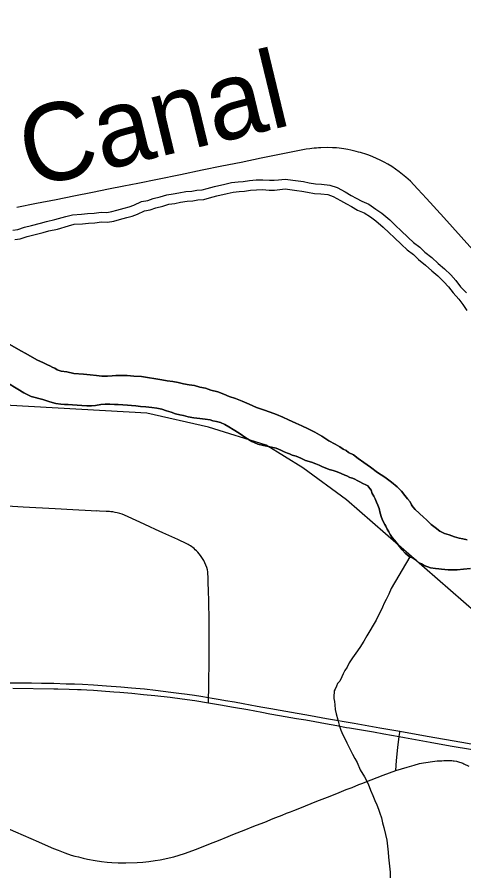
# Model space of a CAD drawing. Extents: x 0 to 34, y -1.2 to 22.
# Drawn here: x 4.736 to 5.172, y 17.227 to 18.067 of the extents above; entities that cross this region are included whole.
import ezdxf

# ---------------------------------------------------------------- set-up
doc = ezdxf.new("R2010")
doc.units = 0
for name, color, linetype in [('GM_X_City_Street', 7, 'Continuous'), ('GM_X_County_Road', 7, 'Continuous'), ('GM_X_Rail_Line', 7, 'Continuous'), ('GM_X_State_Route', 7, 'Continuous'), ('SH_Data', 7, 'Continuous'), ('SH_Text', 7, 'Continuous'), ('UT_X_Telecom', 7, 'Continuous')]:
    doc.layers.add(name, color=color, linetype=linetype)

msp = doc.modelspace()

# ---------------------------------------------------------------- linework, layer by layer
at = {"layer": 'GM_X_City_Street'}
for points in [[(4.70937, 17.59029), (4.74135, 17.58835), (4.7728, 17.58644), (4.79013, 17.5855), (4.80783, 17.58454), (4.8131, 17.58426)], [(4.92269, 17.39645), (4.92269, 17.40167), (4.92294, 17.40926), (4.92301, 17.41883), (4.92325, 17.43444), (4.92346, 17.44977), (4.92334, 17.47715), (4.92321, 17.48481), (4.92314, 17.48809), (4.92299, 17.49699), (4.92289, 17.49976), (4.92274, 17.50258), (4.92262, 17.50636), (4.92248, 17.51386), (4.92238, 17.5163), (4.92229, 17.51879), (4.92216, 17.52365), (4.92207, 17.52375), (4.92199, 17.52452), (4.92159, 17.52659), (4.9209, 17.52905), (4.92012, 17.53108), (4.91914, 17.5334), (4.91804, 17.53563), (4.91744, 17.53673), (4.91623, 17.53875), (4.91563, 17.53966), (4.91499, 17.54054), (4.91365, 17.54226), (4.91219, 17.54388), (4.91101, 17.54509), (4.90978, 17.54627), (4.90853, 17.54742), (4.90733, 17.54845), (4.90627, 17.54917), (4.9051, 17.54994), (4.9039, 17.55068), (4.90269, 17.55139), (4.90152, 17.55205), (4.89251, 17.5563), (4.88972, 17.55746), (4.87785, 17.56289), (4.87078, 17.56614), (4.86532, 17.56869), (4.86041, 17.57086), (4.8554, 17.57326), (4.84065, 17.58001), (4.83823, 17.581), (4.83586, 17.58178), (4.8335, 17.5824), (4.83146, 17.5828), (4.82917, 17.58321), (4.82724, 17.58342), (4.8258, 17.5835), (4.82258, 17.58375), (4.81603, 17.58408), (4.8131, 17.58426)], [(4.8117, 17.24247), (4.81817, 17.24147), (4.8235, 17.24092), (4.82828, 17.24061), (4.83434, 17.24033), (4.84188, 17.24006), (4.85278, 17.24048), (4.85831, 17.24083), (4.86427, 17.24148), (4.87054, 17.24235), (4.87526, 17.24317), (4.88865, 17.24601), (4.89906, 17.24941), (4.91078, 17.25369), (4.92146, 17.25781), (4.92706, 17.26014), (4.93241, 17.26212), (4.942, 17.26602), (4.94654, 17.26779), (4.95065, 17.2694), (4.95487, 17.27112), (4.9593, 17.27285), (4.96536, 17.27524), (4.96951, 17.27697), (4.97405, 17.27873), (4.97932, 17.28067), (4.98418, 17.2827), (4.98849, 17.28446), (4.99459, 17.28678), (4.99889, 17.28859), (5.00273, 17.29005), (5.00621, 17.29144), (5.01193, 17.29372), (5.02308, 17.2981), (5.02867, 17.30032), (5.03391, 17.30234), (5.03888, 17.30432), (5.04479, 17.30673), (5.05027, 17.30898), (5.05731, 17.31172), (5.0631, 17.31396), (5.06964, 17.3167), (5.07364, 17.31817), (5.07763, 17.31969), (5.0816, 17.32125), (5.0933, 17.32592), (5.10595, 17.33053), (5.10657, 17.34028), (5.10774, 17.35282), (5.10917, 17.3637), (5.10964, 17.36757), (5.10979, 17.3688)], [(5.10595, 17.33053), (5.11693, 17.33382), (5.12389, 17.33572), (5.12902, 17.33712), (5.13293, 17.33792), (5.13513, 17.33832), (5.13734, 17.33869), (5.13955, 17.33901), (5.14176, 17.3393), (5.14399, 17.33955), (5.14621, 17.33975), (5.14844, 17.33992), (5.15067, 17.34004), (5.15291, 17.34012), (5.15648, 17.34023), (5.15878, 17.34016), (5.16071, 17.34008), (5.1618, 17.34), (5.16289, 17.33987), (5.16505, 17.33951), (5.16612, 17.33928), (5.16718, 17.339), (5.16823, 17.33869), (5.16927, 17.33834), (5.17029, 17.33795), (5.1713, 17.33752), (5.1723, 17.33707), (5.17716, 17.33453)], [(4.68636, 17.29112), (4.70286, 17.28399), (4.73392, 17.27048), (4.75652, 17.26055), (4.76594, 17.2565), (4.77106, 17.25427), (4.77568, 17.25241), (4.78208, 17.25005), (4.78853, 17.24775), (4.79194, 17.24676), (4.79543, 17.24588), (4.80017, 17.24465), (4.8042, 17.24375), (4.8117, 17.24247)]]:
    msp.add_lwpolyline(points, dxfattribs=at)
at = {"layer": 'GM_X_County_Road'}
msp.add_lwpolyline([(5.18944, 17.83012), (5.16969, 17.85202), (5.15261, 17.87089), (5.13584, 17.88969), (5.12735, 17.89889), (5.12357, 17.90294), (5.12001, 17.90641), (5.11565, 17.91032), (5.11242, 17.91313), (5.10897, 17.91581), (5.10541, 17.91836), (5.10177, 17.92077), (5.09803, 17.92304), (5.09435, 17.92517), (5.09066, 17.92709), (5.08706, 17.92886), (5.08324, 17.93038), (5.07928, 17.93186), (5.07536, 17.93319), (5.07332, 17.93386), (5.07126, 17.93448), (5.06919, 17.93507), (5.0671, 17.93562), (5.06186, 17.93685), (5.0589, 17.93746), (5.05493, 17.93811), (5.05037, 17.93874), (5.04793, 17.939), (5.04402, 17.93927), (5.03948, 17.93936), (5.03253, 17.93923), (5.03031, 17.93911), (5.02813, 17.93895), (5.02595, 17.93875), (5.02378, 17.9385), (5.02162, 17.93821), (5.01831, 17.93779), (5.00853, 17.93597), (4.99683, 17.93366), (4.97404, 17.92889), (4.95474, 17.92497), (4.93556, 17.92108), (4.91653, 17.91722), (4.89522, 17.91289), (4.8727, 17.90833), (4.8535, 17.90444), (4.83981, 17.90165), (4.82487, 17.89872), (4.80913, 17.89552), (4.79109, 17.89184), (4.77378, 17.88832), (4.75456, 17.88457), (4.73523, 17.8808)], dxfattribs=at)
at = {"layer": 'GM_X_Rail_Line'}
msp.add_lwpolyline([(5.36803, 17.32517), (5.35374, 17.3375), (5.21012, 17.46206), (5.05765, 17.59497), (5.01492, 17.62627), (4.97905, 17.6484), (4.92259, 17.66596), (4.8623, 17.6797), (4.56699, 17.69649), (4.4945, 17.70412), (4.44719, 17.71557), (4.40217, 17.73389), (4.35562, 17.75985), (4.31289, 17.79343), (4.27626, 17.83465), (4.23353, 17.89419), (4.02937, 18.17245)], dxfattribs=at)
at = {"layer": 'GM_X_State_Route'}
for points in [[(4.72487, 17.41628), (4.7495, 17.41601), (4.75945, 17.4159), (4.77153, 17.41573)], [(4.77153, 17.41573), (4.78364, 17.41531), (4.79152, 17.41508), (4.79948, 17.41477), (4.81013, 17.41424), (4.8229, 17.41334), (4.83691, 17.41221), (4.84751, 17.41135), (4.85996, 17.41017), (4.87077, 17.40891), (4.8859, 17.40714), (4.89373, 17.40613), (4.90195, 17.40504), (4.90907, 17.40401), (4.91503, 17.403), (4.92269, 17.40167), (4.92609, 17.40109), (4.93419, 17.39984), (4.93921, 17.39891), (4.94798, 17.39743), (4.95663, 17.39579), (4.9702, 17.39342), (4.97584, 17.39244), (4.98368, 17.391), (4.99281, 17.3894), (5.00947, 17.38647), (5.01874, 17.38487), (5.02747, 17.38326), (5.03809, 17.3814), (5.06504, 17.37669), (5.09016, 17.37226), (5.10979, 17.3688), (5.13659, 17.36407), (5.17047, 17.35808), (5.19036, 17.35459)], [(4.73136, 17.4108), (4.77128, 17.41027), (4.77519, 17.41016), (4.78652, 17.40991), (4.7947, 17.4097), (4.79813, 17.40947), (4.80358, 17.40923), (4.81016, 17.40886), (4.81809, 17.40836), (4.83015, 17.40745), (4.83584, 17.40701), (4.84758, 17.40599), (4.85916, 17.40487), (4.87021, 17.4038), (4.88527, 17.40204), (4.897, 17.40046), (4.90923, 17.39872), (4.92269, 17.39645), (4.93444, 17.39455), (4.94707, 17.39238), (4.96101, 17.39), (4.97493, 17.38739), (4.98277, 17.38595), (4.99193, 17.38434), (5.00859, 17.38142), (5.01783, 17.37981), (5.02656, 17.3782), (5.0372, 17.37634), (5.04816, 17.37436), (5.05767, 17.37256), (5.06067, 17.37208), (5.08391, 17.36809), (5.09417, 17.36635), (5.10917, 17.3637), (5.11423, 17.36281), (5.13928, 17.35829), (5.15907, 17.35453), (5.18082, 17.35094)]]:
    msp.add_lwpolyline(points, dxfattribs=at)
at = {"layer": 'SH_Data'}
for points in [[(4.73134, 17.85872), (4.73633, 17.85944), (4.74274, 17.8616), (4.74953, 17.86322), (4.75849, 17.86549), (4.76426, 17.86705), (4.77255, 17.86896), (4.78328, 17.87196), (4.78961, 17.87379), (4.79864, 17.87422), (4.80426, 17.87499), (4.81077, 17.87539), (4.8178, 17.87623), (4.82321, 17.87589), (4.82803, 17.87675), (4.83295, 17.87817), (4.84015, 17.88009), (4.84506, 17.88151), (4.84973, 17.8832), (4.85718, 17.88654), (4.86321, 17.88777), (4.86841, 17.88964), (4.87541, 17.89122), (4.88186, 17.89326), (4.88805, 17.8941), (4.89353, 17.89522), (4.90058, 17.89648), (4.90637, 17.89688), (4.91129, 17.89766), (4.91646, 17.89801), (4.92126, 17.89931), (4.92861, 17.90127), (4.93851, 17.90359), (4.94531, 17.90531), (4.95181, 17.90576), (4.95655, 17.90611), (4.96263, 17.90727), (4.9692, 17.90773), (4.97585, 17.90774), (4.9823, 17.90738), (4.98695, 17.90739), (4.99121, 17.90773), (4.9975, 17.90864), (5.01026, 17.90697), (5.0155, 17.90618), (5.02124, 17.90504), (5.02743, 17.90402), (5.03323, 17.90367), (5.04138, 17.90278), (5.04837, 17.9003), (5.05641, 17.89608), (5.06213, 17.89266), (5.06695, 17.89007), (5.07259, 17.88691), (5.07943, 17.8841), (5.08641, 17.87932), (5.0921, 17.87527), (5.09991, 17.8687), (5.10576, 17.86286), (5.1106, 17.85841), (5.11783, 17.85156), (5.12313, 17.84663), (5.12933, 17.84199), (5.13432, 17.837), (5.14103, 17.8318), (5.14718, 17.82604), (5.15337, 17.82102), (5.15955, 17.81486), (5.16456, 17.80944), (5.1691, 17.8034), (5.17487, 17.79726)], [(4.73325, 17.84942), (4.73855, 17.85019), (4.74536, 17.85249), (4.7518, 17.85402), (4.76089, 17.85632), (4.76656, 17.85786), (4.7749, 17.85978), (4.78588, 17.86284), (4.79118, 17.86438), (4.79951, 17.86478), (4.80519, 17.86555), (4.81163, 17.86595), (4.81807, 17.86672), (4.82375, 17.86636), (4.83019, 17.86751), (4.83549, 17.86905), (4.84268, 17.87096), (4.84798, 17.8725), (4.85328, 17.87441), (4.8601, 17.87746), (4.86578, 17.87862), (4.87108, 17.88053), (4.87789, 17.88207), (4.88395, 17.88398), (4.88963, 17.88476), (4.89531, 17.88591), (4.90175, 17.88706), (4.90743, 17.88746), (4.91235, 17.88823), (4.91803, 17.88863), (4.92371, 17.89016), (4.93091, 17.89208), (4.94075, 17.89438), (4.94681, 17.89591), (4.95249, 17.89631), (4.9578, 17.8967), (4.96385, 17.89786), (4.96954, 17.89825), (4.9756, 17.89827), (4.98204, 17.8979), (4.98734, 17.89792), (4.99227, 17.89831), (4.99757, 17.89908), (5.00894, 17.89759), (5.01387, 17.89684), (5.01955, 17.89571), (5.02637, 17.89459), (5.03243, 17.89423), (5.03925, 17.89348), (5.04456, 17.8916), (5.05177, 17.88782), (5.05746, 17.88441), (5.06239, 17.88177), (5.06846, 17.87836), (5.07491, 17.87572), (5.08098, 17.87155), (5.08629, 17.86777), (5.0935, 17.86171), (5.0992, 17.85602), (5.10413, 17.85148), (5.11135, 17.84466), (5.11704, 17.83935), (5.12311, 17.83481), (5.12805, 17.82988), (5.13488, 17.82458), (5.14095, 17.8189), (5.14703, 17.81397), (5.15272, 17.80829), (5.15728, 17.80336), (5.16184, 17.79729), (5.16754, 17.79123), (5.17134, 17.78592), (5.17514, 17.78023)], [(5.11955, 17.53947), (5.10113, 17.50842), (5.09893, 17.5027), (5.09634, 17.49772), (5.0945, 17.4939), (5.09265, 17.49008), (5.09081, 17.48588), (5.08859, 17.48167), (5.08675, 17.47747), (5.07747, 17.46215), (5.0745, 17.4568), (5.07079, 17.45067), (5.06669, 17.4453), (5.06333, 17.4407), (5.06036, 17.43572), (5.05814, 17.43152), (5.05591, 17.42807), (5.05444, 17.42501), (5.05296, 17.42195), (5.05112, 17.41775), (5.04887, 17.41544), (5.04777, 17.41277), (5.04667, 17.41009), (5.04555, 17.40818), (5.04558, 17.40628), (5.04523, 17.404), (5.04527, 17.40096), (5.0457, 17.39792), (5.04612, 17.39451), (5.04656, 17.38995), (5.04738, 17.38578), (5.04898, 17.3801), (5.05057, 17.3748), (5.05215, 17.36988), (5.05411, 17.36534), (5.05645, 17.36119), (5.05802, 17.35741), (5.05997, 17.35363), (5.06153, 17.35023), (5.06348, 17.34645), (5.06582, 17.3423), (5.06816, 17.33815), (5.07091, 17.33096), (5.07518, 17.32417), (5.07869, 17.31738), (5.08105, 17.31132), (5.0834, 17.30603), (5.08537, 17.30112), (5.08732, 17.29696), (5.0889, 17.2928), (5.09009, 17.28863), (5.09167, 17.28409), (5.09288, 17.27916), (5.09408, 17.27462), (5.0957, 17.2678), (5.09691, 17.26249), (5.09775, 17.25642), (5.09821, 17.25073), (5.09865, 17.24579), (5.10038, 17.23099), (5.10045, 17.22567)]]:
    msp.add_lwpolyline(points, dxfattribs=at)
at = {"layer": 'UT_X_Telecom'}
for points in [[(4.76745, 17.72595), (4.76516, 17.72706), (4.76133, 17.72892), (4.75484, 17.73188), (4.74642, 17.73672), (4.73685, 17.74192), (4.72843, 17.74676)], [(4.72843, 17.74676), (4.73685, 17.74192), (4.74642, 17.73672), (4.75484, 17.73188), (4.76133, 17.72892), (4.76516, 17.72706), (4.76745, 17.72595)], [(5.17566, 17.55606), (5.17147, 17.55677), (5.16766, 17.55749), (5.16309, 17.55895), (5.15813, 17.56079), (5.15355, 17.56226), (5.14897, 17.56448), (5.14436, 17.56785), (5.14052, 17.57084), (5.13822, 17.57309), (5.13591, 17.57535), (5.13283, 17.57797), (5.12476, 17.58547), (5.12244, 17.58811), (5.12128, 17.58999), (5.11972, 17.59301), (5.1174, 17.59602), (5.1147, 17.59941), (5.11122, 17.60355), (5.10699, 17.60768), (5.10161, 17.61217), (5.09509, 17.61704), (5.08781, 17.62189), (5.0809, 17.62713), (5.07439, 17.63161), (5.06902, 17.63534), (5.06441, 17.63909), (5.05945, 17.64131), (5.05714, 17.64318), (5.05446, 17.64467), (5.05102, 17.64691), (5.04642, 17.64951), (5.0403, 17.65286), (5.03341, 17.65734), (5.02652, 17.66105), (5.02002, 17.66439), (5.01391, 17.66736), (5.00818, 17.66995), (5.00092, 17.67329), (4.99519, 17.67588), (4.98908, 17.67846), (4.98297, 17.68067), (4.97648, 17.68287), (4.96962, 17.68545), (4.96236, 17.6884), (4.95549, 17.69136), (4.949, 17.69394), (4.94289, 17.69615), (4.93755, 17.69836), (4.93182, 17.70057), (4.92496, 17.70239), (4.91962, 17.70423), (4.91429, 17.7053), (4.90895, 17.70676), (4.90363, 17.70745), (4.8983, 17.70853), (4.89297, 17.7096), (4.88764, 17.71068), (4.88231, 17.71138), (4.87698, 17.71245), (4.8572, 17.71563), (4.8496, 17.71592), (4.84313, 17.7166), (4.83744, 17.71653), (4.83213, 17.71647), (4.82833, 17.71642), (4.82378, 17.71599), (4.81846, 17.71592), (4.81314, 17.71662), (4.80705, 17.71731), (4.80059, 17.71799), (4.79109, 17.71863), (4.78423, 17.72007), (4.77853, 17.72076), (4.77471, 17.72224), (4.77241, 17.72373), (4.77051, 17.72447), (4.76745, 17.72595)], [(4.76745, 17.72595), (4.77051, 17.72447), (4.77241, 17.72373), (4.77471, 17.72224), (4.77853, 17.72076), (4.78423, 17.72007), (4.79109, 17.71863), (4.80059, 17.71799), (4.80705, 17.71731), (4.81314, 17.71662), (4.81846, 17.71592), (4.82378, 17.71599), (4.82833, 17.71642), (4.83213, 17.71647), (4.83744, 17.71653), (4.84313, 17.7166), (4.8496, 17.71592), (4.8572, 17.71563), (4.87698, 17.71245), (4.88231, 17.71138), (4.88764, 17.71068), (4.89297, 17.7096), (4.8983, 17.70853), (4.90363, 17.70745), (4.90895, 17.70676), (4.91429, 17.7053), (4.91962, 17.70423), (4.92496, 17.70239), (4.93182, 17.70057), (4.93755, 17.69836), (4.94289, 17.69615), (4.949, 17.69394), (4.95549, 17.69136), (4.96236, 17.6884), (4.96962, 17.68545), (4.97648, 17.68287), (4.98297, 17.68067), (4.98908, 17.67846), (4.99519, 17.67588), (5.00092, 17.67329), (5.00818, 17.66995), (5.01391, 17.66736), (5.02002, 17.66439), (5.02652, 17.66105), (5.03341, 17.65734), (5.0403, 17.65286), (5.04642, 17.64951), (5.05102, 17.64691), (5.05446, 17.64467), (5.05714, 17.64318), (5.05945, 17.64131), (5.06441, 17.63909), (5.06902, 17.63534), (5.07439, 17.63161), (5.0809, 17.62713), (5.08781, 17.62189), (5.09509, 17.61704), (5.10161, 17.61217), (5.10699, 17.60768), (5.11122, 17.60355), (5.1147, 17.59941), (5.1174, 17.59602), (5.11972, 17.59301), (5.12128, 17.58999), (5.12244, 17.58811), (5.12476, 17.58547), (5.13283, 17.57797), (5.13591, 17.57535), (5.13822, 17.57309), (5.14052, 17.57084), (5.14436, 17.56785), (5.14897, 17.56448), (5.15355, 17.56226), (5.15813, 17.56079), (5.16309, 17.55895), (5.16766, 17.55749), (5.17147, 17.55677), (5.17566, 17.55606)], [(4.72552, 17.70986), (4.73625, 17.70315), (4.74199, 17.6998), (4.74925, 17.69609), (4.76068, 17.69319), (4.76755, 17.69099), (4.77327, 17.68916), (4.77821, 17.68846), (4.78202, 17.68812), (4.78543, 17.68817), (4.78961, 17.68784), (4.79417, 17.68751), (4.79873, 17.68718), (4.80367, 17.68686), (4.80823, 17.68692), (4.81202, 17.68734), (4.81732, 17.68817), (4.8215, 17.6886), (4.82605, 17.68866), (4.83061, 17.68833), (4.83441, 17.68838), (4.83897, 17.68805), (4.84353, 17.68773), (4.84733, 17.68739), (4.85151, 17.68706), (4.85608, 17.68636), (4.8614, 17.68604), (4.8671, 17.68535), (4.87205, 17.68465), (4.877, 17.68357), (4.88158, 17.6821), (4.88615, 17.68064), (4.89035, 17.67917), (4.89454, 17.67808), (4.89834, 17.67737)], [(4.89834, 17.67737), (4.89454, 17.67808), (4.89035, 17.67917), (4.88615, 17.68064), (4.88158, 17.6821), (4.877, 17.68357), (4.87205, 17.68465), (4.8671, 17.68535), (4.8614, 17.68604), (4.85608, 17.68636), (4.85151, 17.68706), (4.84733, 17.68739), (4.84353, 17.68773), (4.83897, 17.68805), (4.83441, 17.68838), (4.83061, 17.68833), (4.82605, 17.68866), (4.8215, 17.6886), (4.81732, 17.68817), (4.81202, 17.68734), (4.80823, 17.68692), (4.80367, 17.68686), (4.79873, 17.68718), (4.79417, 17.68751), (4.78961, 17.68784), (4.78543, 17.68817), (4.78202, 17.68812), (4.77821, 17.68846), (4.77327, 17.68916), (4.76755, 17.69099), (4.76068, 17.69319), (4.74925, 17.69609), (4.74199, 17.6998), (4.73625, 17.70315), (4.72552, 17.70986)], [(4.89834, 17.67737), (4.90292, 17.67628), (4.90825, 17.67521), (4.91433, 17.67452), (4.91928, 17.67382), (4.92422, 17.67312), (4.92689, 17.67239), (4.93032, 17.67167), (4.93451, 17.67058), (4.93871, 17.66873), (4.94254, 17.6665), (4.94675, 17.66389), (4.9525, 17.66016), (4.95901, 17.65568), (4.96514, 17.65195), (4.97087, 17.64936), (4.97658, 17.64829), (4.98877, 17.6454), (4.99335, 17.64355), (4.99679, 17.64207), (4.99985, 17.64059), (5.00175, 17.63985), (5.00443, 17.63875), (5.00824, 17.63765), (5.01282, 17.63581), (5.01741, 17.63358), (5.02351, 17.63175), (5.0277, 17.63029), (5.03076, 17.6288), (5.0342, 17.62732), (5.03687, 17.62622), (5.04069, 17.62474), (5.0445, 17.62365), (5.04831, 17.62255), (5.05252, 17.6207), (5.05595, 17.61923), (5.05786, 17.61849), (5.06092, 17.617), (5.06359, 17.61628), (5.06588, 17.61517), (5.06817, 17.61405), (5.07047, 17.61256), (5.07353, 17.61108), (5.07659, 17.60959), (5.07849, 17.60886), (5.08043, 17.60622), (5.08159, 17.60433), (5.08277, 17.60131), (5.08433, 17.59867), (5.08551, 17.59602), (5.08707, 17.59262), (5.08825, 17.58997), (5.08943, 17.58657), (5.09063, 17.58202), (5.09183, 17.57786), (5.09302, 17.57445), (5.09496, 17.57105), (5.09613, 17.56917), (5.0973, 17.56652), (5.09886, 17.56388), (5.10041, 17.56124), (5.10235, 17.55822), (5.10466, 17.55559), (5.11201, 17.54617), (5.11509, 17.54279), (5.11893, 17.5398), (5.12313, 17.53757), (5.12581, 17.53608), (5.12812, 17.53383), (5.1308, 17.53234), (5.13348, 17.53085), (5.13958, 17.52865), (5.14453, 17.52795), (5.14795, 17.52761), (5.15061, 17.52726), (5.15366, 17.52692), (5.15708, 17.52658), (5.16125, 17.52663), (5.16581, 17.52668), (5.17188, 17.52714), (5.1787, 17.52798)], [(5.1787, 17.52798), (5.17188, 17.52714), (5.16581, 17.52668), (5.16125, 17.52663), (5.15708, 17.52658), (5.15366, 17.52692), (5.15061, 17.52726), (5.14795, 17.52761), (5.14453, 17.52795), (5.13958, 17.52865), (5.13348, 17.53085), (5.1308, 17.53234), (5.12812, 17.53383), (5.12581, 17.53608), (5.12313, 17.53757), (5.11893, 17.5398), (5.11509, 17.54279), (5.11201, 17.54617), (5.10466, 17.55559), (5.10235, 17.55822), (5.10041, 17.56124), (5.09886, 17.56388), (5.0973, 17.56652), (5.09613, 17.56917), (5.09496, 17.57105), (5.09302, 17.57445), (5.09183, 17.57786), (5.09063, 17.58202), (5.08943, 17.58657), (5.08825, 17.58997), (5.08707, 17.59262), (5.08551, 17.59602), (5.08433, 17.59867), (5.08277, 17.60131), (5.08159, 17.60433), (5.08043, 17.60622), (5.07849, 17.60886), (5.07659, 17.60959), (5.07353, 17.61108), (5.07047, 17.61256), (5.06817, 17.61405), (5.06588, 17.61517), (5.06359, 17.61628), (5.06092, 17.617), (5.05786, 17.61849), (5.05595, 17.61923), (5.05252, 17.6207), (5.04831, 17.62255), (5.0445, 17.62365), (5.04069, 17.62474), (5.03687, 17.62622), (5.0342, 17.62732), (5.03076, 17.6288), (5.0277, 17.63029), (5.02351, 17.63175), (5.01741, 17.63358), (5.01282, 17.63581), (5.00824, 17.63765), (5.00443, 17.63875), (5.00175, 17.63985), (4.99985, 17.64059), (4.99679, 17.64207), (4.99335, 17.64355), (4.98877, 17.6454), (4.97658, 17.64829), (4.97087, 17.64936), (4.96514, 17.65195), (4.95901, 17.65568), (4.9525, 17.66016), (4.94675, 17.66389), (4.94254, 17.6665), (4.93871, 17.66873), (4.93451, 17.67058), (4.93032, 17.67167), (4.92689, 17.67239), (4.92422, 17.67312), (4.91928, 17.67382), (4.91433, 17.67452), (4.90825, 17.67521), (4.90292, 17.67628), (4.89834, 17.67737)]]:
    msp.add_lwpolyline(points, dxfattribs=at)

# ---------------------------------------------------------------- texts
at = {"layer": 'SH_Text'}
msp.add_text('Canal', height=0.075799, rotation=13.58108, dxfattribs=at).set_placement((4.74807, 17.89976))

doc.saveas('drawing.dxf')
